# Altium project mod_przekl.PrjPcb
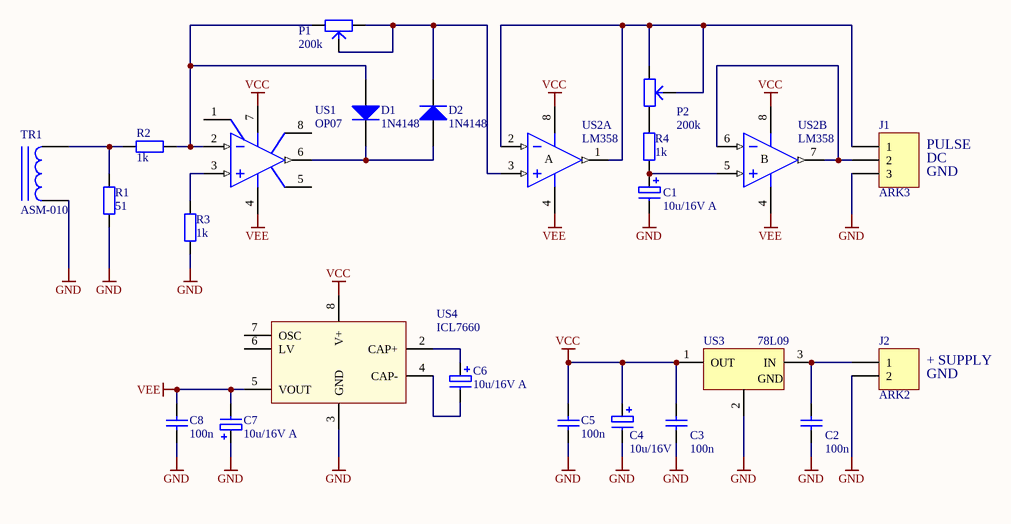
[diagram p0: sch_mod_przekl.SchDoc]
1 sheet, 23 parts. Net scope: global (net labels, ports and power ports of the same name join across sheets).
Board file: pcb_mod_przekl.PcbDoc

## Sheet sch_mod_przekl.SchDoc
size A3

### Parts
C1  10u/16V A  [Tantal A 3216-1206]
C2  100n  [MELF-1206]
C3  100n  [MELF-1206]
C4  10u/16V  [Tantal A 3216-1206]
C5  100n  [MELF-1206]
C6  10u/16V A  [Tantal A 3216-1206]
C7  10u/16V A  [Tantal A 3216-1206]
C8  100n  [MELF-1206]
D1  1N4148  [dioda MINIMELF]
D2  1N4148  [dioda MINIMELF]
J1  ARK3  [ARK3 5mm]
J2  ARK2  [ARK2 5mm]
P1  200k  [helitrim 5x10mm]
P2  200k  [helitrim 5x10mm]
R1  51  [MELF-1206]
R2  1k  [MELF-1206]
R3  1k  [MELF-1206]
R4  1k  [MELF-1206]
TR1  ASM-010  [TALEMA AS10x]
US1  OP07  [Q-8]
US2  LM358  [JG008]  (parts A,B of 2)
US3  78L09  [29-04]
US4  ICL7660  [DIP8]

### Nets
GND: C1.2 C2.1 C3.1 C4.2 C5.1 C7.1 C8.1 J1.3 J2.2 R1.1 R3.1 TR1.1 US3.2(GND) US4.3(GND)
VCC: C3.2 C4.1 C5.2 US1.7(V+) US2.8(V+) US3.1(OUT) US4.8(V+)
VEE: C7.2 C8.2 US1.4(V-) US2.4(V-) US4.5(VOUT)
NetC1_1: C1.1 R4.1 US2.5(IN+)
NetC2_2: C2.2 J2.1 US3.3(IN)
NetC6_1: C6.1 US4.2(CAP+)
NetC6_2: C6.2 US4.4(CAP-)
NetD1_1: D1.1(A) P1.b R2.2 US1.2(IN-)
NetD1_2: D1.2(K) D2.1(A) US1.6(OUT)
NetD2_2: D2.2(K) P1.a P1.c US2.3(IN+)
NetJ1_1: J1.1 P2.a P2.c US2.1(OUT) US2.2(IN-)
NetJ1_2: J1.2 US2.6(IN-) US2.7(OUT)
NetP2_b: P2.b R4.2
NetR1_2: R1.2 R2.1 TR1.2
NetR3_2: R3.2 US1.3(IN+)

Not connected (* = marked no-connect by the designer): US1 1(VOSTRIM) 5(NC) 8(VOSTRIM); US4 6(LV) 7(OSC)

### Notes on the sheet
- (near J1) GND
- (near J1) DC
- (near J1) PULSE
- (near J2) GND
- (near J2) + SUPPLY

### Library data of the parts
C1 C4 C6 C7 = kond biegunowy: Polarized Capacitor
C2 C3 C5 C8 = kondensator
D1 D2 = Diode: Default Diode
P1 P2 = pot mont
R1-R4 = rezystor
TR1 = przekładnik prądowy
US1 = OP07EZ: Ultra-Low Offset Voltage Operational Amplifier; Note: Pin 5 is not connected.
US2 = LM358JG: Dual Operational Amplifier
US3 = MC78L05ACP: 3-Terminal Low-Current Positive Fixed Voltage Regulator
